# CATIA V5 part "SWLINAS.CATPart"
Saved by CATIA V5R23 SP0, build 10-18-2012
Part number: Part3
Bounding box of the stored display mesh (mm): x 0 to 24, y -1 to 1, z -1 to 1
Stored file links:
  G:\STOIXEIO_SINDESIS\SWLINAS.CATPart
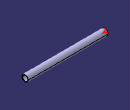
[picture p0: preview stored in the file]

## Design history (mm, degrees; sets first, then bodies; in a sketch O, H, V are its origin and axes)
WSupportSet1: ActiveGrid {3dwsupport RefPoint {point stored without definition}, 3DWOS ({wsupport Support xy-plane, RefPoint {3dwsupport}, GridIn {cartgrid Value 100, Stepbid1 0, Value 100, Stepbid2 0, Direction (1, 0, 0)}, GeometricData ({line type PtDir, Direction (1, 0, 0), Support xy-plane}; {line type PtDir, Direction (0, 1, 0), Support yz-plane})}; {wsupport Support yz-plane, RefPoint {3dwsupport}, GridIn {cartgrid Value 100, Stepbid1 0, Value 100, Stepbid2 0, Direction (0, 1, 0)}, GeometricData ({line type PtDir, Direction (0, 1, 0), Support yz-plane}; {line type PtDir, Direction (0, 0, 1), Support zx-plane})}; {wsupport Support zx-plane, RefPoint {3dwsupport}, GridIn {cartgrid Value 100, Stepbid1 0, Value 100, Stepbid2 0, Direction (0, 0, 1)}, GeometricData ({line type PtDir, Direction (0, 0, 1), Support zx-plane}; {line type PtDir, Direction (1, 0, 0), Support xy-plane})}), GeometricData ({line type PtDir, RefPoint {point stored without definition}, Direction (1, 0, 0), Support xy-plane}; {line type PtDir, RefPoint {point stored without definition}, Direction (0, 1, 0), Support yz-plane}; {line type PtDir, RefPoint {point stored without definition}, Direction (0, 0, 1), Support zx-plane})}
AxisSystem1: origin (0, 0, 0), X (1, 0, 0), Y (0, 1, 0), Z (0, 0, 1)
Body1 (main body)
  Sketch1 on yz-plane, origin (0, 0, 0), H (0, 1, 0), V (0, 0, 1)
    circle A1 centre (0, 0) radius 1
    point P1 (0, -1)
    circle A2 centre (0, 0) radius 0.8
    point P2 (0, -0.8)
    coincidence: A1 P1, P1 V, A2 P2, P2 V
  Pad1: profile Sketch1, direction (1, 0, 0), length 24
